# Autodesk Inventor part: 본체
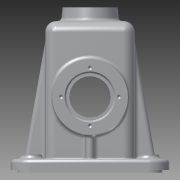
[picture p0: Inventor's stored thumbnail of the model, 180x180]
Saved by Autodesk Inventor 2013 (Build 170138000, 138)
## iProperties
Created: 2016-01
Part Number: 본체
Material: 알루미늄 6061
Document SubType Name: Modeling
Designer: User
Mass: 857.084 g
Surface Area: 924.112 cm^2
Volume: 316.267 cm^3
Density: 2.71 g/cm^3
Author: User
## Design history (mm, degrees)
sketch "스케치1"
  geometry: L1 (-32.5, 32.5)-(32.5, 32.5); L2 (32.5, 32.5)-(32.5, -32.5); L3 (32.5, -32.5)-(-32.5, -32.5); L4 (-32.5, -32.5)-(-32.5, 32.5); L5 (-32.5, 32.5)-(32.5, -32.5); L6 (32.5, 32.5)-(-32.5, -32.5); 1 further point
  constraints: 12 end point, 2 midpoint, 2 parallel, 1 horizontal, 1 perpendicular
  dimensions: "d0" = 65 distance of L2.end L3.end; "d1" = 65 distance of L1.end L2.end
extrude "돌출1" new body sketch "스케치1" distance "d2" = 110; taper "d3" = 0 deg
sketch "스케치2" dims "d82" = 15
  geometry: L1 (-57.5, 65)-(57.5, 65); L2 (57.5, 65)-(57.5, -65); L3 (57.5, -65)-(-57.5, -65); L4 (-57.5, -65)-(-57.5, 65); L5 (-57.5, 65)-(57.5, -65); L6 (57.5, 65)-(-57.5, -65); 1 further point
  constraints: 12 end point, 2 midpoint, 2 parallel, 1 horizontal, 1 perpendicular
  dimensions: "d4" = 115 distance of L2.end L3.end; "d5" = 130 distance of L1.end L2.end
extrude "돌출2" join sketch "스케치2" distance "d6" = 10; taper "d7" = 0 deg
sketch "스케치3"
  geometry: L1 (-57.5, 65)-(57.5, 65) reference; L2 (-57.5, -65)-(-57.5, 65) reference; L3 (57.5, -65)-(-57.5, -65) reference; L4 (57.5, 65)-(57.5, -65) reference; L5 (52.5, 60)-(-52.5, 60); L6 (-52.5, 60)-(-52.5, -60); L7 (-52.5, -60)-(52.5, -60); L8 (52.5, -60)-(52.5, 60); 1 further point
  constraints: 8 end point, 3 other
  dimensions: "d8" = 5 distance between parallel lines of L5 L1
extrude "돌출3" cut sketch "스케치3" distance "d9" = 2; taper "d10" = 0 deg
fillet "모깎기1" dims "d11" = 15
fillet "모깎기2" dims "d12" = 15
sketch "스케치4"
  geometry: L1 (-65, 10)-(-32.5, 10) reference; L2 (-32.5, 10)-(-32.5, 110) reference; L3 (-32.5, 110)-(32.5, 110) reference; L4 (32.5, 110)-(32.5, 10) reference; L5 (32.5, 10)-(65, 10) reference; L6 (65, 10)-(65, 2) reference; L7 (65, 2)-(60, 2) reference; L8 (60, 2)-(60, 0) reference; L9 (60, 0)-(-60, 0) reference; L10 (-60, 0)-(-60, 2) reference; L11 (-60, 2)-(-65, 2) reference; L12 (-65, 2)-(-65, 10) reference; L13 (27.5, 105)-(27.5, 0); L14 (27.5, 105)-(-27.5, 105); L15 (-27.5, 105)-(-27.5, 0); 1 further point
  constraints: 6 end point, 2 perpendicular, 2 point on line, 1 vertical
  dimensions: "d13" = 5 distance between parallel lines of L4 L13; "d14" = 5 distance between parallel lines of L2 L15; "d15" = 5 distance between parallel lines of L3 L14
extrude "돌출4" cut sketch "스케치4" stored distance "d16" = 55; taper "d17" = 0 deg
sketch "스케치5"
  geometry: L1 (0, 0)-(65, 0) reference; L2 (70, -110)-(-5, -110) reference; C1 r 27.5 at (32.5, -55); 2 further points
  constraints: 1 centre point, 1 midpoint, 1 vertical alignment
  dimensions: "d18" = 55 diameter of C1; "d19" = 55 distance from line of L2 C1.centre
extrude "돌출5" join sketch "스케치5" distance "d20" = 15; taper "d21" = 0 deg
sketch "스케치6"
  geometry: L1 (-52.742, 55)-(52.163, 55); L2 (-30.5, 72.5)-(-30.5, 70); L3 (30.5, 70)-(30.5, 72.5); L4 (-65, 10)-(-32.5, 10) reference; L5 (-32.5, 10)-(-32.5, 27.5) reference; L6 (-32.5, 27.5)-(-47.5, 27.5) reference; L7 (-47.5, 27.5)-(-47.5, 82.5) reference; L8 (-47.5, 82.5)-(-32.5, 82.5) reference; L9 (-32.5, 82.5)-(-32.5, 110) reference; L10 (-32.5, 110)-(32.5, 110) reference; L11 (32.5, 110)-(32.5, 82.5) reference; L12 (32.5, 82.5)-(47.5, 82.5) reference; L13 (47.5, 82.5)-(47.5, 27.5) reference; L14 (47.5, 27.5)-(32.5, 27.5) reference; L15 (32.5, 27.5)-(32.5, 10) reference; L16 (32.5, 10)-(65, 10) reference; L17 (65, 10)-(65, 2) reference; L18 (65, 2)-(60, 2) reference; L19 (60, 2)-(60, 0) reference; L20 (60, 0)-(27.5, 0) reference; L21 (27.5, 0)-(27.5, 105) reference; L22 (27.5, 105)-(-27.5, 105) reference; L23 (-27.5, 105)-(-27.5, 0) reference; L24 (-27.5, 0)-(-60, 0) reference; L25 (-60, 0)-(-60, 2) reference; L26 (-60, 2)-(-65, 2) reference; L27 (-65, 2)-(-65, 10) reference; L28 (-30.5, 72.5)-(-47.5, 72.5); L29 (30.5, 72.5)-(47.5, 72.5); L30 (-47.5, 72.5)-(-47.5, 55); L31 (47.5, 72.5)-(47.5, 55); L32 (-30.5, 70)-(-27.5, 70); L33 (-27.5, 70)-(-27.5, 55); L34 (30.5, 72.5)-(30.5, 70); L35 (30.5, 70)-(27.5, 70); L36 (27.5, 70)-(27.5, 55); L37 (-47.5, 55)-(-27.5, 55); L38 (27.5, 55)-(47.5, 55); 1 further point
  constraints: 28 end point, 8 point on line, 4 perpendicular, 2 collinear, 2 midpoint, 2 parallel, 1 horizontal
  dimensions: "d22" = 55 distance from line of point (0, 0) L1; "d23" = 35 diameter of L28 L1; "d25" = 17 distance of L2.start L28.end; "d26" = 17 distance of L3.end L29.end; "d27" = 61 distance between parallel lines of L2 L3; "d28" = 30 diameter of L32 L1
  node "절단 모서리 투영2"
revolve "회전1" stored, may be unused: angle "d29" = 90 deg
revolve "회전2" stored, may be unused: angle "d30" = 90 deg
sketch "스케치7"
  geometry: C1 r 20 at (0, 0); 1 further point
  constraints: 1 centre point, 1 coincident
  dimensions: "d31" = 40 diameter of C1
extrude "돌출6" join sketch "스케치7" distance "d32" = 10; taper "d33" = 0 deg
feature "면 기울기1" dims angle "d34" = 5 deg
sketch "스케치8"
  geometry: C1 r 20 at (0, 0) reference; C2 r 10.5 at (0, 0)
  constraints: 1 centre point, 1 coincident
  dimensions: "d35" = 21 diameter of C2
extrude "돌출7" cut sketch "스케치8" distance "d36" = 20.75; taper "d37" = 0 deg
sketch "스케치9" dims "d38" = 29
  geometry: C1 r 20 at (0, 0) reference; 2 further points
  constraints: 2 vertical alignment, 1 coincident, 2 other
hole "구멍1" sketch "스케치9" at (0, 14.5) diameter "d39" = 2.459; stored, may be unused: countersink angle "d43" = 90 deg, drill point angle "d45" = 118 deg; dims "d40" = 7, "d41" = 4, "d42" = 2, "d44" = 9
sketch "스케치10" dims "d49" = 42
  geometry: C1 r 27.5 at (0, 0) reference; 3 further points
  constraints: 2 horizontal alignment, 1 coincident, 2 other
hole "구멍2" sketch "스케치10" at (21, 0) diameter "d50" = 3.242; stored, may be unused: countersink angle "d54" = 90 deg, drill point angle "d56" = 118 deg; dims "d51" = 8, "d52" = 4, "d53" = 2, "d55" = 10
sketch "스케치11"
  geometry: L1 (27.5, 0)-(27.5, 105) reference; L2 (27.5, 105)-(10.5, 105) reference; L3 (10.5, 105)-(10.5, 120) reference; L4 (10.5, 120)-(13.27, 120) reference; L5 (13.27, 120)-(13.27, 111) reference; L6 (13.27, 111)-(14.5, 110.261) reference; L7 (14.5, 110.261)-(15.73, 111) reference; L8 (15.73, 111)-(15.73, 120) reference; L9 (15.73, 120)-(20, 120) reference; L10 (20, 120)-(20.875, 110) reference; L11 (20.875, 110)-(32.5, 110) reference; L12 (32.5, 110)-(32.5, 10) reference; L13 (32.5, 10)-(57.5, 10) reference; L14 (57.5, 10)-(57.5, 2) reference; L15 (57.5, 2)-(52.5, 2) reference; L16 (52.5, 2)-(52.5, 0) reference; L17 (52.5, 0)-(27.5, 0) reference; L18 (-52.5, 2)-(-57.5, 2) reference; L19 (-57.5, 2)-(-57.5, 10) reference; L20 (-57.5, 10)-(-32.5, 10) reference; L21 (-32.5, 10)-(-32.5, 110) reference; L22 (-32.5, 110)-(-20.875, 110) reference; L23 (-20.875, 110)-(-20, 120) reference; L24 (-20, 120)-(-15.73, 120) reference; L25 (-15.73, 120)-(-15.73, 111) reference; L26 (-15.73, 111)-(-14.5, 110.261) reference; L27 (-14.5, 110.261)-(-13.27, 111) reference; L28 (-13.27, 111)-(-13.27, 120) reference; L29 (-13.27, 120)-(-10.5, 120) reference; L30 (-10.5, 120)-(-10.5, 105) reference; L31 (-10.5, 105)-(-27.5, 105) reference; L32 (-27.5, 105)-(-27.5, 0) reference; L33 (-27.5, 0)-(-52.5, 0) reference; L34 (-52.5, 0)-(-52.5, 2) reference; L35 (-32.5, 95.069)-(-47.5, 10); L36 (47.5, 10)-(32.5, 95.069); 1 further point
  constraints: 4 end point, 4 point on line
  dimensions: "d60" = 10 deg angle of L35 L19; "d61" = 10 distance from line of L35.end L19; "d62" = 10 distance of L13.end L36.start; "d63" = 10 deg angle of L14 L36
  node "절단 모서리 투영3"
feature "리브1" dims "d64" = 1, "d65" = 10, "d66" = 0, "d67" = 0, "d68" = 1, "d69" = 1
feature "리브2" dims "d70" = 1, "d71" = 10, "d72" = 0, "d73" = 0, "d74" = 1, "d75" = 1
sketch "스케치12"
  geometry: L1 (-52.5, 45)-(-52.5, -45) reference; L2 (37.5, 60)-(-37.5, 60) reference; L3 (-27.5, 27.5)-(27.5, 27.5) reference; L4 (-42.5, 50)-(42.5, 50); L5 (-42.5, 50)-(-42.5, -50); C1 r 3 at (-42.5, 50); C2 r 3 at (42.5, 50); C3 r 3 at (-42.5, -50); C4 r 3 at (42.5, -50); 5 further points
  constraints: 4 centre point, 4 end point, 4 midpoint, 3 vertical alignment, 2 horizontal alignment, 1 parallel, 1 perpendicular
  dimensions: "d76" = 6 diameter of C2; "d77" = 6 diameter of C1; "d78" = 6 diameter of C3; "d79" = 6 diameter of C4; "d80" = 85 distance of L4.end L4.start; "d81" = 100 distance of L5.end L4.start
sketch "스케치13"
  geometry: C1 r 3 at (-42.5, -50) reference; C2 r 3 at (-42.5, 50) reference; C3 r 3 at (42.5, 50) reference; C4 r 3 at (42.5, -50) reference; C5 r 7.5 at (-42.5, -50); C6 r 7.5 at (42.5, -50); C7 r 7.5 at (-42.5, 50); C8 r 7.5 at (42.5, 50); 1 further point
  constraints: 4 centre point, 4 coincident
  dimensions: "d82" = 15 diameter of C5; "d83" = 15 diameter of C6; "d84" = 15 diameter of C7; "d85" = 15 diameter of C8
extrude "돌출8" join sketch "스케치13" distance "d86" = 3; taper "d87" = 0 deg
hole "구멍3" sketch "스케치12" diameter "d88" = 6; stored, may be unused: countersink angle "d92" = 90 deg, drill point angle "d94" = 118 deg; dims "d89" = 8, "d90" = 4, "d91" = 2, "d93" = 10
chamfer "모따기1" distance "d95" = 1; stored, may be unused: second distance "d96" = 2, angle "d97" = 45 deg
fillet "모깎기3" dims "d98" = 8
fillet "모깎기4" dims "d99" = 8
sketch "스케치14"
  geometry: L1 (30.5, 70)-(27.5, 70) reference; L2 (27.5, 70)-(27.5, 105) reference; L3 (27.5, 105)-(10.5, 105) reference; L4 (10.5, 105)-(10.5, 119) reference; L5 (10.5, 119)-(11.5, 120) reference; L6 (11.5, 120)-(13.27, 120) reference; L7 (13.27, 120)-(13.27, 111) reference; L8 (13.27, 111)-(14.5, 110.261) reference; L9 (14.5, 110.261)-(15.73, 111) reference; L10 (15.73, 111)-(15.73, 120) reference; L11 (15.73, 120)-(20, 120) reference; L12 (20, 120)-(20.875, 110) reference; L13 (20.875, 110)-(24.5, 110) reference; L14 (32.5, 102)-(32.5, 82.5) reference; L15 (32.5, 82.5)-(47.5, 82.5) reference; L16 (47.5, 82.5)-(47.5, 77.621) reference; L17 (47.5, 77.621)-(37.5, 77.621) reference; L18 (37.5, 77.621)-(36.526, 76) reference; L19 (36.526, 76)-(37.5, 74.379) reference; L20 (37.5, 74.379)-(47.5, 74.379) reference; L21 (47.5, 74.379)-(47.5, 73.5) reference; L22 (47.5, 73.5)-(46.5, 72.5) reference; L23 (46.5, 72.5)-(30.5, 72.5) reference; L24 (30.5, 72.5)-(30.5, 70) reference; L25 (27.5, 40)-(30.5, 40) reference; L26 (30.5, 40)-(30.5, 37.5) reference; L27 (30.5, 37.5)-(46.5, 37.5) reference; L28 (46.5, 37.5)-(47.5, 36.5) reference; L29 (47.5, 36.5)-(47.5, 35.621) reference; L30 (47.5, 35.621)-(37.5, 35.621) reference; L31 (37.5, 35.621)-(36.526, 34) reference; L32 (36.526, 34)-(37.5, 32.379) reference; L33 (37.5, 32.379)-(47.5, 32.379) reference; L34 (47.5, 32.379)-(47.5, 27.5) reference; L35 (47.5, 27.5)-(32.5, 27.5) reference; L36 (32.5, 27.5)-(32.5, 10) reference; L37 (32.5, 10)-(65, 10) reference; L38 (65, 10)-(65, 2) reference; L39 (65, 2)-(60, 2) reference; L40 (60, 2)-(60, 0) reference; L41 (60, 0)-(27.5, 0) reference; L42 (27.5, 0)-(27.5, 40) reference; L43 (-27.5, 70)-(-30.5, 70) reference; L44 (-30.5, 70)-(-30.5, 72.5) reference; L45 (-30.5, 72.5)-(-46.5, 72.5) reference; L46 (-46.5, 72.5)-(-47.5, 73.5) reference; L47 (-47.5, 73.5)-(-47.5, 74.379) reference; L48 (-47.5, 74.379)-(-37.5, 74.379) reference; L49 (-37.5, 74.379)-(-36.526, 76) reference; L50 (-36.526, 76)-(-37.5, 77.621) reference; L51 (-37.5, 77.621)-(-47.5, 77.621) reference; L52 (-47.5, 77.621)-(-47.5, 82.5) reference; L53 (-47.5, 82.5)-(-32.5, 82.5) reference; L54 (-32.5, 82.5)-(-32.5, 102) reference; L55 (-24.5, 110)-(-20.875, 110) reference; L56 (-20.875, 110)-(-20, 120) reference; L57 (-20, 120)-(-15.73, 120) reference; L58 (-15.73, 120)-(-15.73, 111) reference; L59 (-15.73, 111)-(-14.5, 110.261) reference; L60 (-14.5, 110.261)-(-13.27, 111) reference; L61 (-13.27, 111)-(-13.27, 120) reference; L62 (-13.27, 120)-(-11.5, 120) reference; L63 (-11.5, 120)-(-10.5, 119) reference; L64 (-10.5, 119)-(-10.5, 105) reference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; A1 r 8 centre (24.5, 102) between (32.5, 102) and (24.5, 110) reference; A2 r 8 centre (-24.5, 102) between (-24.5, 110) and (-32.5, 102) reference; 1 further point
  constraints: 4 end point, 4 point on line, 2 parallel
  dimensions: "d100" = 15 distance between parallel lines of L68 L85; "d101" = 15 distance between parallel lines of L86 L42
  node "절단 모서리 투영4"
feature "리브3" dims "d102" = 1, "d103" = 6, "d104" = 0, "d105" = 0, "d106" = 1, "d107" = 1
feature "리브4" dims "d108" = 1, "d109" = 6, "d110" = 0, "d111" = 0, "d112" = 1, "d113" = 1
fillet "모깎기5" dims "d114" = 3
fillet "모깎기6" dims "d115" = 3
fillet "모깎기7" dims "d116" = 3
fillet "모깎기8" dims "d117" = 3
fillet "모깎기9" dims "d118" = 3
sketch "스케치15"
  geometry: L1 (57, 0)-(57, 92) reference; L2 (4.5, -18)-(44.5, -18) reference; 3 further points
  constraints: 1 other
  dimensions: "d120" = 32.5 distance from line of point (24.5, 8) L1; "d121" = 26 distance from line of point (24.5, 8) L2
feature "엠보싱1" sketch "스케치15" dims "d122" = 0.5, "d123" = 0
fillet "모깎기11" dims "d124" = 3
fillet "모깎기12" dims "d125" = 0.3
fillet "모깎기13" dims "d126" = 1
sketch "스케치16"
  geometry: L1 (-37.5, -60)-(37.5, -60) reference; L2 (52.5, -45)-(52.5, 45) reference; L3 (37.5, 60)-(-37.5, 60) reference; L4 (-52.5, 45)-(-52.5, -45) reference; L5 (-24.5, 27.5)-(24.5, 27.5) reference; L6 (27.5, 24.5)-(27.5, -24.5) reference; L7 (24.5, -27.5)-(-24.5, -27.5) reference; L8 (-27.5, -24.5)-(-27.5, 24.5) reference; C1 r 3 at (42.5, 50) reference; C2 r 3 at (-42.5, -50) reference; C3 r 3 at (42.5, -50) reference; C4 r 3 at (-42.5, 50) reference; A1 r 15 centre (37.5, -45) between (37.5, -60) and (52.5, -45) reference; A2 r 15 centre (37.5, 45) between (52.5, 45) and (37.5, 60) reference; A3 r 15 centre (-37.5, 45) between (-37.5, 60) and (-52.5, 45) reference; A4 r 15 centre (-37.5, -45) between (-52.5, -45) and (-37.5, -60) reference; A5 r 3 centre (24.5, 24.5) between (27.5, 24.5) and (24.5, 27.5) reference; A6 r 3 centre (24.5, -24.5) between (24.5, -27.5) and (27.5, -24.5) reference; A7 r 3 centre (-24.5, -24.5) between (-27.5, -24.5) and (-24.5, -27.5) reference; A8 r 3 centre (-24.5, 24.5) between (-24.5, 27.5) and (-27.5, 24.5) reference; 1 further point
extrude "돌출9" cut sketch "스케치16" distance "d127" = 2; taper "d128" = 0 deg
sketch "스케치17"
  geometry: L1 (24.5, 27.5)-(-24.5, 27.5) reference; L2 (27.5, -24.5)-(27.5, 24.5) reference; L3 (-24.5, -27.5)-(24.5, -27.5) reference; L4 (-27.5, 24.5)-(-27.5, -24.5) reference; L5 (42.5, -65)-(-42.5, -65) reference; L6 (57.5, 50)-(57.5, -50) reference; L7 (-42.5, 65)-(42.5, 65) reference; L8 (-57.5, -50)-(-57.5, 50) reference; L9 (52.5, 50)-(52.5, -50); L10 (42.5, -60)-(-42.5, -60); L11 (-52.5, -50)-(-52.5, 50); L12 (-42.5, 60)-(42.5, 60); C1 r 3 at (42.5, 50) reference; C2 r 3 at (-42.5, -50) reference; C3 r 3 at (42.5, -50) reference; C4 r 3 at (-42.5, 50) reference; A1 r 3 centre (-24.5, 24.5) between (-24.5, 27.5) and (-27.5, 24.5) reference; A2 r 3 centre (24.5, 24.5) between (27.5, 24.5) and (24.5, 27.5) reference; A3 r 3 centre (24.5, -24.5) between (24.5, -27.5) and (27.5, -24.5) reference; A4 r 3 centre (-24.5, -24.5) between (-27.5, -24.5) and (-24.5, -27.5) reference; A5 r 15 centre (42.5, -50) between (42.5, -65) and (57.5, -50) reference; A6 r 15 centre (42.5, 50) between (57.5, 50) and (42.5, 65) reference; A7 r 15 centre (-42.5, 50) between (-42.5, 65) and (-57.5, 50) reference; A8 r 15 centre (-42.5, -50) between (-57.5, -50) and (-42.5, -65) reference; A9 r 10 centre (42.5, 50) between (52.5, 50) and (42.5, 60); A10 r 10 centre (42.5, -50) between (42.5, -60) and (52.5, -50); A11 r 10 centre (-42.5, -50) between (-52.5, -50) and (-42.5, -60); A12 r 10 centre (-42.5, 50) between (-42.5, 60) and (-52.5, 50); 1 further point
  constraints: 8 end point, 8 point on circle, 4 centre point, 7 other
  dimensions: "d129" = 5 distance between parallel lines of L5 L10
extrude "돌출10" join sketch "스케치17" distance "d130" = 2; taper "d131" = 0 deg
node "솔리드1"
mirror "대칭1"
pattern_circular "원형 패턴1" dims angle "d47" = 360 deg
pattern_circular "원형 패턴2" dims angle "d58" = 360 deg
mirror "대칭2"
node "절단 모서리 투영1"
